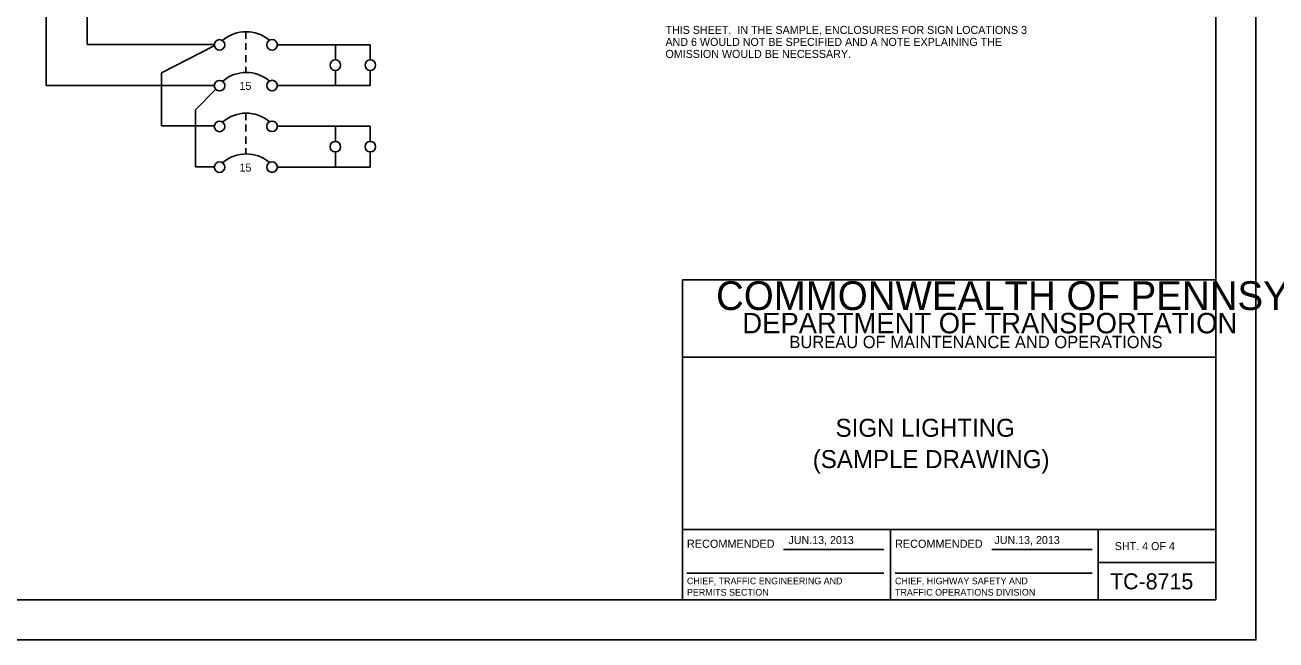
# Model space of a CAD drawing. Extents: x 36 to 2622, y -5330 to 219.
# Drawn here: x 1256.4 to 1725.4, y -5329.8 to -5099.2 of the extents above; entities that cross this region are included whole.
import ezdxf

# ---------------------------------------------------------------- set-up
doc = ezdxf.new("R2010")
doc.units = 0
for name, color, linetype in [('1', 7, 'Continuous'), ('2', 7, 'Continuous'), ('PLT-BNDY', 7, 'Continuous')]:
    doc.layers.add(name, color=color, linetype=linetype)

msp = doc.modelspace()

# ---------------------------------------------------------------- linework, layer by layer
at = {"layer": '1'}
for p, q in [((1702.86, -5314.83), (1702.86, -4750.83)), ((1502.86, -5314.83), (1502.86, -5194.83)), ((1502.86, -5194.83), (1702.86, -5194.83)), ((1702.86, -5223.83), (1502.86, -5223.83)), ((1502.86, -5288.45), (1702.86, -5288.45)), ((1580.86, -5288.45), (1580.86, -5314.83)), ((1658.73, -5314.83), (1658.73, -5288.45)), ((1540.79, -5295.88), (1578.41, -5295.88)), ((1618.79, -5295.88), (1656.41, -5295.88)), ((1658.73, -5300.83), (1702.86, -5300.83)), ((1504.54, -5304.78), (1578.41, -5304.78)), ((1582.54, -5304.78), (1656.41, -5304.78)), ((1702.86, -5314.83), (916.86, -5314.83)), ((916.86, -5314.83), (1502.86, -5314.83))]:
    msp.add_line(p, q, dxfattribs=at)
at = {"layer": '2'}
for p, q in [((1264.31, -4831.83), (1264.31, -5121.95)), ((1279.68, -4831.83), (1279.68, -5106.58)), ((1339.18, -5101.83), (1339.18, -5104.45)), ((1327.31, -5106.58), (1279.68, -5106.58)), ((1339.18, -5108.58), (1339.18, -5106.08)), ((1350.93, -5106.7), (1385.81, -5106.7)), ((1372.81, -5106.7), (1372.81, -5112.33)), ((1385.81, -5106.7), (1385.81, -5112.33)), ((1327.31, -5107.08), (1307.56, -5117.2)), ((1339.18, -5113.2), (1339.18, -5110.58)), ((1339.18, -5117.08), (1339.18, -5114.95)), ((1307.56, -5137.08), (1307.56, -5117.2)), ((1372.81, -5121.95), (1372.81, -5116.2)), ((1385.81, -5121.95), (1385.81, -5116.2)), ((1264.31, -5121.95), (1327.31, -5121.95)), ((1327.93, -5123.33), (1320.31, -5131.08)), ((1385.81, -5121.95), (1350.93, -5121.95)), ((1320.31, -5152.45), (1320.31, -5131.08)), ((1339.18, -5132.33), (1339.18, -5134.95)), ((1327.31, -5137.08), (1307.56, -5137.08)), ((1339.18, -5139.2), (1339.18, -5136.58)), ((1350.93, -5137.2), (1385.81, -5137.2)), ((1372.81, -5137.2), (1372.81, -5142.83)), ((1385.81, -5137.2), (1385.81, -5142.83)), ((1339.18, -5143.83), (1339.18, -5141.08)), ((1339.18, -5147.58), (1339.18, -5145.45)), ((1372.81, -5152.58), (1372.81, -5146.83)), ((1385.81, -5152.58), (1385.81, -5146.83)), ((1327.31, -5152.45), (1320.31, -5152.45)), ((1350.93, -5152.58), (1385.81, -5152.58))]:
    msp.add_line(p, q, dxfattribs=at)
for centre in [(1329.34, -5106.71), (1349.02, -5106.67), (1372.73, -5114.31), (1385.86, -5114.31), (1329.34, -5121.99), (1349.02, -5121.95), (1329.34, -5137.27), (1349.02, -5137.23), (1372.73, -5144.87), (1385.86, -5144.87), (1329.34, -5152.55), (1349.02, -5152.51)]:
    msp.add_circle(centre, 1.98, dxfattribs=at)
for centre in [(1339.33, -5115.17), (1339.33, -5130.45), (1339.33, -5145.72), (1339.33, -5161)]:
    msp.add_arc(centre, 13.42, 49.9422, 130.6112, dxfattribs=at)
at = {"layer": 'PLT-BNDY'}
msp.add_lwpolyline([(876.86, -4735.83), (1717.86, -4735.83), (1717.86, -5329.83), (876.86, -5329.83)], close=True, dxfattribs=at)

# ---------------------------------------------------------------- texts
at = {"layer": '1'}
for s, height, p in [('COMMONWEALTH OF PENNSYLVANIA', 10.7828, (1515.45, -5206.1)), ('DEPARTMENT OF TRANSPORTATION', 7.6837, (1525.31, -5214.85)), ('BUREAU OF MAINTENANCE AND OPERATIONS', 4.6253, (1542.95, -5220.41)), ('SIGN LIGHTING', 6.75, (1560.26, -5253.64)), ('(SAMPLE DRAWING)', 6.75, (1551.7, -5265.39)), ('RECOMMENDED', 3.048, (1504.54, -5295.26)), ('RECOMMENDED', 3.048, (1582.54, -5295.26)), ('SHT. 4 OF 4', 3, (1664.94, -5296.14)), ('CHIEF, TRAFFIC ENGINEERING AND', 2.5, (1504.54, -5308.94)), ('CHIEF, HIGHWAY SAFETY AND', 2.5, (1582.54, -5308.94)), ('TC-8715', 6, (1663.14, -5310.83)), ('PERMITS SECTION', 2.5, (1504.54, -5313.19)), ('TRAFFIC OPERATIONS DIVISION', 2.5, (1582.54, -5313.19))]:
    msp.add_text(s, height=height, dxfattribs=at).set_placement(p)
at = {"layer": '2'}
for s, height, p in [('    THIS SHEET.  IN THE SAMPLE, ENCLOSURES FOR SIGN LOCATIONS 3', 3, (1492.03, -5102.58)), ('    AND 6 WOULD NOT BE SPECIFIED AND A NOTE EXPLAINING THE', 3, (1492.03, -5107.08)), ('    OMISSION WOULD BE NECESSARY.', 3, (1492.03, -5111.58)), ('15', 2.996, (1336.81, -5123.58)), ('15', 2.996, (1336.81, -5154.2)), ('JUN.13, 2013', 2.9955, (1542.59, -5293.86)), ('JUN.13, 2013', 2.9955, (1619.81, -5293.86))]:
    msp.add_text(s, height=height, dxfattribs=at).set_placement(p)

doc.saveas('drawing.dxf')
